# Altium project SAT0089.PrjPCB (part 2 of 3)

## Sheet CAMERA 2.SchDoc
size 431 x 279 mm; Date: Not shown in title block; ApprovedBy: Not shown in title block; CheckedBy: Not shown in title block; Author: Not shown in title block; CompanyName: Not shown in title block; DrawnBy: G. Fiolic; Engineer: Not shown in title block; Organization: Not shown in title block; Address1: Not shown in title block; Address2: Not shown in title block; Address3: Not shown in title block; Address4: Not shown in title block; DocumentNumber: 6; Revision: Use project parameter SCH_Rev; SheetNumber: 6; SheetTotal: 11; PageSetup: Record=PageOptions|CenterHorizontal=True|CenterVertical=True|PrintScale=1.00|XCorrection=1.00|YCorrection=1.00|PrintKind=0|BorderSize=5000000|LeftOffset=0|BottomOffset=0|Orientation=2|PaperLength=1000|PaperWidth=1000|Scale=100|PaperSource=15|PrintQuality=600|MediaType=1|DitherType=10|PaperKind=Letter|PrintScaleMode=1
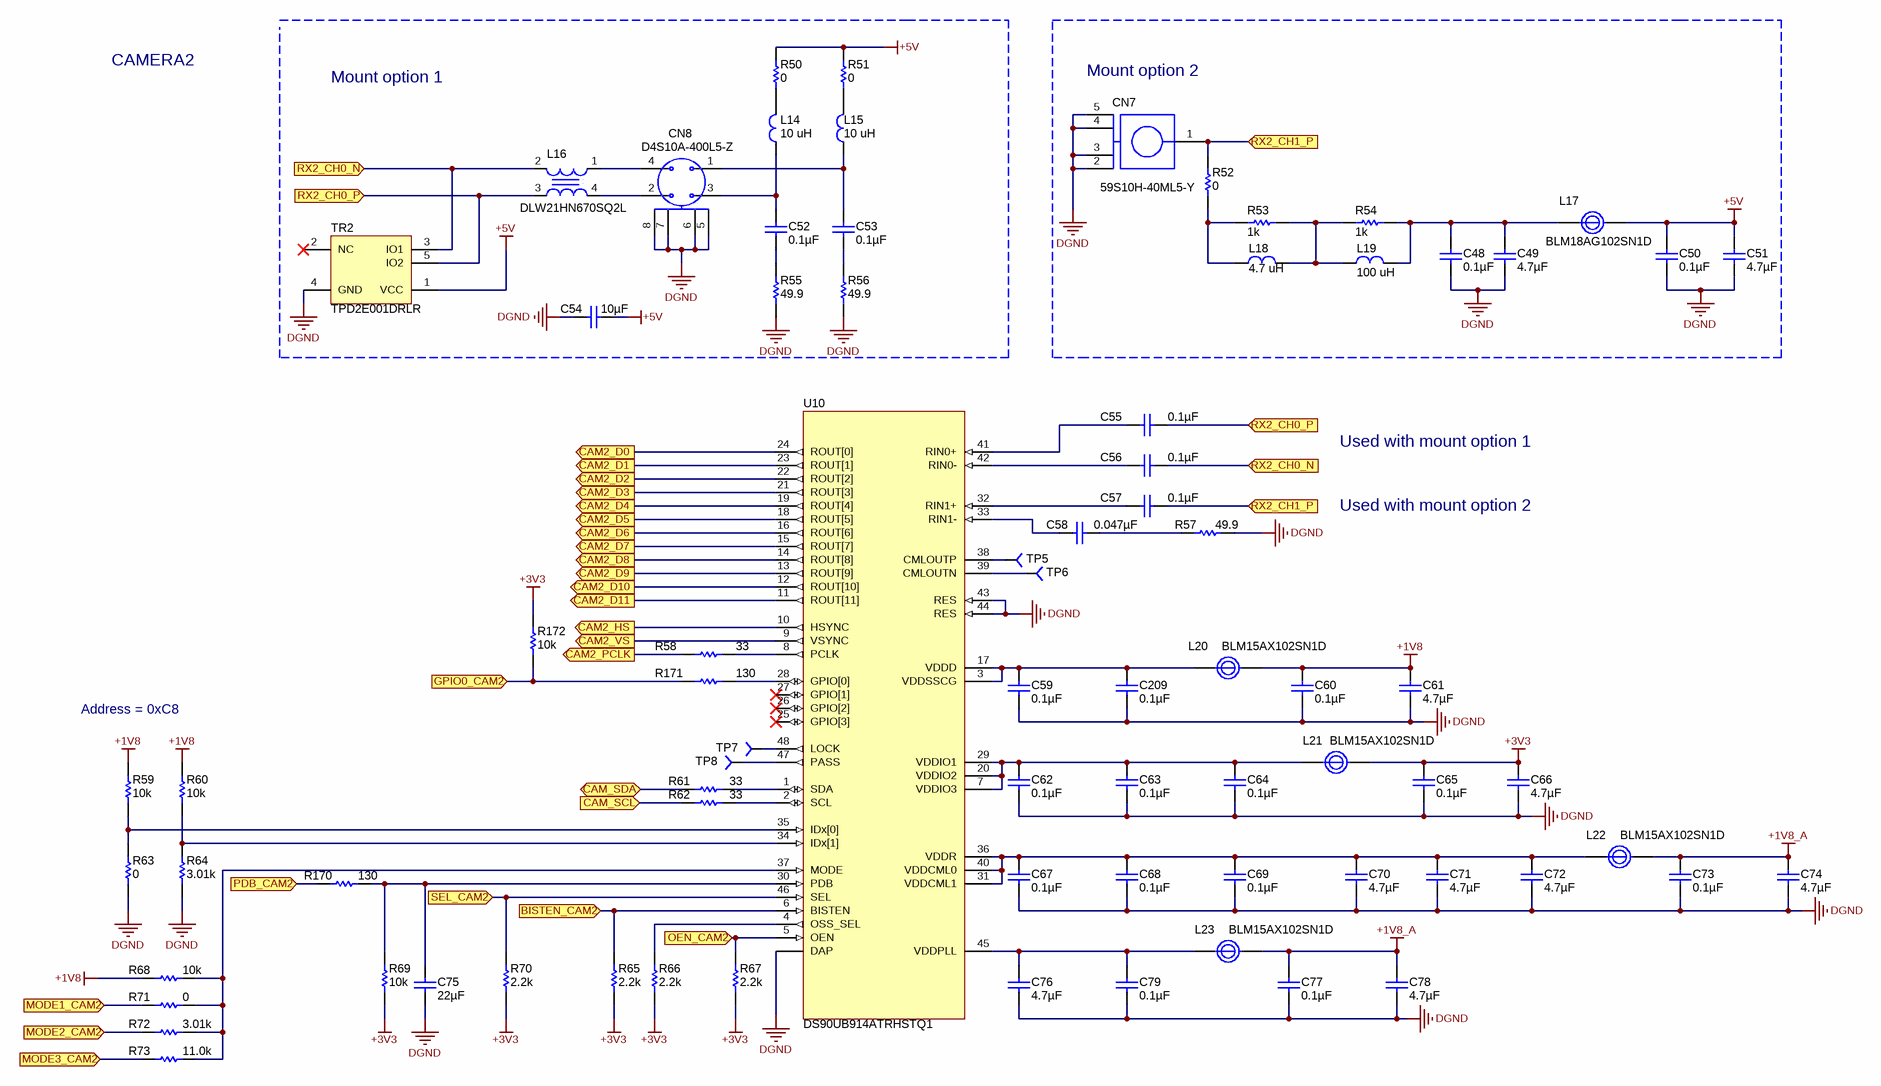
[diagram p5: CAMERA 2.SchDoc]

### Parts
C48  ValueDisplayed: 0.1µF  [0402L]  (hidden comment: GRM155R71C104KA88D)
C49  value 4.7µF  [0603L]  (hidden comment: GRM188R61E475KE11D)
C50  ValueDisplayed: 0.1µF  [0402L]  (hidden comment: GRM155R71C104KA88D)
C51  value 4.7µF  [0603L]  (hidden comment: GRM188R61E475KE11D)
C52  value 0.1µF  [0603L]  (hidden comment: GRM188R72A104KA35D)
C53  value 0.1µF  [0603L]  (hidden comment: GRM188R72A104KA35D)
C54  ValueDisplayed: 10µF  [0805L]  (hidden comment: GRM21BR61C106KE15L)
C55  ValueDisplayed: 0.1µF  [0402L]  (hidden comment: GRM155R71C104KA88D)
C56  ValueDisplayed: 0.1µF  [0402L]  (hidden comment: GRM155R71C104KA88D)
C57  ValueDisplayed: 0.1µF  [0402L]  (hidden comment: GRM155R71C104KA88D)
C58  ValueDisplayed: 0.047µF  [0402L]  (hidden comment: GRM155R71C473KA01D)
C59  ValueDisplayed: 0.1µF  [0402L]  (hidden comment: GRM155R71C104KA88D)
C60  ValueDisplayed: 0.1µF  [0402L]  (hidden comment: GRM155R71C104KA88D)
C61  value 4.7µF  [0603L]  (hidden comment: GRM188R61E475KE11D)
C62  ValueDisplayed: 0.1µF  [0402L]  (hidden comment: GRM155R71C104KA88D)
C63  ValueDisplayed: 0.1µF  [0402L]  (hidden comment: GRM155R71C104KA88D)
C64  ValueDisplayed: 0.1µF  [0402L]  (hidden comment: GRM155R71C104KA88D)
C65  ValueDisplayed: 0.1µF  [0402L]  (hidden comment: GRM155R71C104KA88D)
C66  value 4.7µF  [0603L]  (hidden comment: GRM188R61E475KE11D)
C67  ValueDisplayed: 0.1µF  [0402L]  (hidden comment: GRM155R71C104KA88D)
C68  ValueDisplayed: 0.1µF  [0402L]  (hidden comment: GRM155R71C104KA88D)
C69  ValueDisplayed: 0.1µF  [0402L]  (hidden comment: GRM155R71C104KA88D)
C70  value 4.7µF  [0603L]  (hidden comment: GRM188R61E475KE11D)
C71  value 4.7µF  [0603L]  (hidden comment: GRM188R61E475KE11D)
C72  value 4.7µF  [0603L]  (hidden comment: GRM188R61E475KE11D)
C73  ValueDisplayed: 0.1µF  [0402L]  (hidden comment: GRM155R71C104KA88D)
C74  value 4.7µF  [0603L]  (hidden comment: GRM188R61E475KE11D)
C75  ValueDisplayed: 22µF  [0805L]  (hidden comment: JMK212BJ226KG-T)
C76  value 4.7µF  [0603L]  (hidden comment: GRM188R61E475KE11D)
C77  ValueDisplayed: 0.1µF  [0402L]  (hidden comment: GRM155R71C104KA88D)
C78  value 4.7µF  [0603L]  (hidden comment: GRM188R61E475KE11D)
C79  ValueDisplayed: 0.1µF  [0402L]  (hidden comment: GRM155R71C104KA88D)
C209  ValueDisplayed: 0.1µF  [0402L]  (hidden comment: GRM155R71C104KA88D)
CN7  59S10H-40ML5-Y  [59S10H-40ML5-Y]
CN8  D4S10A-400L5-Z  [D4S10A-400L5-Z]
L14  ValueDisplayed: 10 uH  [1008PS-103KLB]  (hidden comment: 1008PS-103KLB)
L15  ValueDisplayed: 10 uH  [1008PS-103KLB]  (hidden comment: 1008PS-103KLB)
L16  DLW21HN670SQ2L  [DLW21HN670SQ2L]
L17  BLM18AG102SN1D  [0603L]
L18  ValueDisplayed: 4.7 uH  [1008PS-472KLB]  (hidden comment: 1008PS-472KLB)
L19  ValueDisplayed: 100 uH  [MSS7341T-104MLB]  (hidden comment: MSS7341T-104MLB)
L20  BLM15AX102SN1D  [0402L]
L21  BLM15AX102SN1D  [0402L]
L22  BLM15AX102SN1D  [0402L]
L23  BLM15AX102SN1D  [0402L]
R50  value 0  [0805L]  (hidden comment: CRCW08050000Z0EA)
R51  value 0  [0805L]  (hidden comment: CRCW08050000Z0EA)
R52  value 0  [0805L]  (hidden comment: CRCW08050000Z0EA)
R53  value 1k  [0603L]  (hidden comment: RC0603JR-071KL)
R54  value 1k  [0603L]  (hidden comment: RC0603JR-071KL)
R55  value 49.9  [0402L]  (hidden comment: CRCW040249R9FKED)
R56  value 49.9  [0402L]  (hidden comment: CRCW040249R9FKED)
R57  value 49.9  [0402L]  (hidden comment: CRCW040249R9FKED)
R58  value 33  [0402L]  (hidden comment: CRCW040233R0JNED)
R59  value 10k  [0402L]  (hidden comment: ERA-2AEB103X)
R60  value 10k  [0402L]  (hidden comment: ERA-2AEB103X)
R61  value 33  [0402L]  (hidden comment: CRCW040233R0JNED)
R62  value 33  [0402L]  (hidden comment: CRCW040233R0JNED)
R63  value 0  [0402L]  (hidden comment: CRCW04020000Z0ED)
R64  value 3.01k  [0402L]  (hidden comment: CRCW04023K01FKED)
R65  value 2.2k  [0402L]  (hidden comment: CRCW04022K20JNED)
R66  value 2.2k  [0402L]  (hidden comment: CRCW04022K20JNED)
R67  value 2.2k  [0402L]  (hidden comment: CRCW04022K20JNED)
R68  value 10k  [0402L]  (hidden comment: ERA-2AEB103X)
R69  value 10k  [0402L]  (hidden comment: ERA-2AEB103X)
R70  value 2.2k  [0402L]  (hidden comment: CRCW04022K20JNED)
R71  value 0  [0402L]  (hidden comment: CRCW04020000Z0ED)
R72  value 3.01k  [0402L]  (hidden comment: CRCW04023K01FKED)
R73  value 11.0k  [0402L]  (hidden comment: CRCW040211K0FKED)
R170  value 130  [0402L]  (hidden comment: CRCW0402130RJNED)
R171  value 130  [0402L]  (hidden comment: CRCW0402130RJNED)
R172  value 10k  [0402L]  (hidden comment: ERA-2AEB103X)
TP5  STD  [TP-032_RND]  (value not drawn)
TP6  STD  [TP-032_RND]  (value not drawn)
TP7  STD  [TP-032_RND]  (value not drawn)
TP8  STD  [TP-032_RND]  (value not drawn)
TR2  TPD2E001DRLR  [DRL0005A]
U10  DS90UB914ATRHSTQ1  [RHS0048A]

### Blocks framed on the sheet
Mount option 2: C48-C51 CN7 L17-L19 R52-R54

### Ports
BISTEN_CAM2 (in), CAM2_D0 (out), CAM2_D1 (out), CAM2_D2 (out), CAM2_D3 (out), CAM2_D4 (out), CAM2_D5 (out), CAM2_D6 (out), CAM2_D7 (out), CAM2_D8 (out), CAM2_D9 (out), CAM2_D10 (out), CAM2_D11 (out), CAM2_HS (out), CAM2_PCLK (out), CAM2_VS (out), CAM_SCL (in), CAM_SDA (bidir), GPIO0_CAM2 (in), MODE1_CAM2 (in), MODE2_CAM2 (in), MODE3_CAM2 (in), OEN_CAM2 (in), PDB_CAM2 (in), RX2_CH0_N (in), RX2_CH0_P (in), RX2_CH1_P (in), SEL_CAM2 (in)

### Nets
+1V8: C60.1 C61.1 L20.2 R59.1 R60.1 R68.1
+1V8_A: C73.1 C74.1 C77.1 C78.1 L22.2 L23.2
+3V3: C65.1 C66.1 L21.2 R65.2 R66.2 R67.2 R69.1 R70.1 R172.1
+5V: C50.1 C51.1 C54.1 L17.2 R50.2 R51.2 TR2.1(VCC)
DGND: C48.2 C49.2 C50.2 C51.2 C54.2 C59.2 C60.2 C61.2 C62.2 C63.2 C64.2 C65.2 C66.2 C67.2 C68.2 C69.2 C70.2 C71.2 C72.2 C73.2 C74.2 C75.2 C76.2 C77.2 C78.2 C79.2 C209.2 CN7.2 CN7.3 CN7.4 CN7.5 CN8.5 CN8.6 CN8.7 CN8.8 R55.1 R56.1 R57.2 R63.2 R64.2 TR2.4(GND) U10.43(RES) U10.44(RES) U10.49(DAP)
BISTEN_CAM2: R65.1 U10.6(BISTEN) ; port BISTEN_CAM2
CAM2_D0: U10.24(ROUT[0]) ; port CAM2_D0
CAM2_D1: U10.23(ROUT[1]) ; port CAM2_D1
CAM2_D2: U10.22(ROUT[2]) ; port CAM2_D2
CAM2_D3: U10.21(ROUT[3]) ; port CAM2_D3
CAM2_D4: U10.19(ROUT[4]) ; port CAM2_D4
CAM2_D5: U10.18(ROUT[5]) ; port CAM2_D5
CAM2_D6: U10.16(ROUT[6]) ; port CAM2_D6
CAM2_D7: U10.15(ROUT[7]) ; port CAM2_D7
CAM2_D8: U10.14(ROUT[8]) ; port CAM2_D8
CAM2_D9: U10.13(ROUT[9]) ; port CAM2_D9
CAM2_D10: U10.12(ROUT[10]) ; port CAM2_D10
CAM2_D11: U10.11(ROUT[11]) ; port CAM2_D11
CAM2_HS: U10.10(HSYNC) ; port CAM2_HS
CAM2_PCLK: R58.1 ; port CAM2_PCLK
CAM2_VS: U10.9(VSYNC) ; port CAM2_VS
CAM_SCL: R62.1 ; port CAM_SCL
CAM_SDA: R61.2 ; port CAM_SDA
GPIO0_CAM2: R171.1 R172.2 ; port GPIO0_CAM2
MODE1_CAM2: R71.1 ; port MODE1_CAM2
MODE2_CAM2: R72.1 ; port MODE2_CAM2
MODE3_CAM2: R73.1 ; port MODE3_CAM2
OEN_CAM2: R67.1 U10.5(OEN) ; port OEN_CAM2
PDB_CAM2: R170.1 ; port PDB_CAM2
RX2_CH0_N: C56.2 L16.2(IN2) TR2.3(IO1) ; port RX2_CH0_N
RX2_CH0_P: C55.2 L16.3(OUT2) TR2.5(IO2) ; port RX2_CH0_P
RX2_CH1_P: C57.2 CN7.1 R52.2 ; port RX2_CH1_P
SEL_CAM2: R70.2 U10.46(SEL) ; port SEL_CAM2
NetC48_1: C48.1 C49.1 L17.1 L19.2 R54.2
NetC52_1: C52.1 CN8.3 L14.1
NetC52_2: C52.2 R55.2
NetC53_1: C53.1 CN8.1 L15.1
NetC53_2: C53.2 R56.2
NetC55_1: C55.1 U10.41(RIN0+)
NetC56_1: C56.1 U10.42(RIN0-)
NetC57_1: C57.1 U10.32(RIN1+)
NetC58_1: C58.1 R57.1
NetC58_2: C58.2 U10.33(RIN1-)
NetC59_1: C59.1 C209.1 L20.1 U10.3(VDDSSCG) U10.17(VDDD)
NetC62_1: C62.1 C63.1 C64.1 L21.1 U10.7(VDDIO3) U10.20(VDDIO2) U10.29(VDDIO1)
NetC67_1: C67.1 C68.1 C69.1 C70.1 C71.1 C72.1 L22.1 U10.31(VDDCML1) U10.36(VDDR) U10.40(VDDCML0)
NetC75_1: C75.1 R69.2 R170.2 U10.30(PDB)
NetC76_1: C76.1 C79.1 L23.1 U10.45(VDDPLL)
NetCN8_2: CN8.2 L16.4(OUT1)
NetCN8_4: CN8.4 L16.1(IN1)
NetL14_2: L14.2 R50.1
NetL15_2: L15.2 R51.1
NetL18_1: L18.1 R52.1 R53.1
NetL18_2: L18.2 L19.1 R53.2 R54.1
NetR58_2: R58.2 U10.8(PCLK)
NetR59_2: R59.2 R63.1 U10.35(IDx[0])
NetR60_2: R60.2 R64.1 U10.34(IDx[1])
NetR61_1: R61.1 U10.1(SDA)
NetR62_2: R62.2 U10.2(SCL)
NetR66_1: R66.1 U10.4(OSS_SEL)
NetR68_2: R68.2 R71.2 R72.2 R73.2 U10.37(MODE)
NetR171_2: R171.2 U10.28(GPIO[0])
NetTP5_1: TP5.1 U10.38(CMLOUTP)
NetTP6_1: TP6.1 U10.39(CMLOUTN)
NetTP7_1: TP7.1 U10.48(LOCK)
NetTP8_1: TP8.1 U10.47(PASS)

Not connected (* = marked no-connect by the designer): TR2 2(NC)*; U10 25(GPIO[3])* 26(GPIO[2])* 27(GPIO[1])*

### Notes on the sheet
- CAMERA2
- Mount option 1
- Used with mount option 1
- Used with mount option 2
- Address = 0xC8

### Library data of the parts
C48 C50 C55-C57 C59 C60 C62-C65 C67-C69 C73 C77 C79 C209 = GRM155R71C104KA88D: CAP, CERM, 0.1uF, 16V, +/-10%, X7R, 0402; Manufacturer: MuRata; Polarized: N; CompType: Capacitor; U/M: EA; Cap_F: 0.0000001; Tolerance_%: 10; Value1: Unknown; VDC_V: 16; TaMin_C: -55; TaMax_C: 125; Cap_Case: 0402
C49 C51 C61 C66 C70-C72 C74 C76 C78 = GRM188R61E475KE11D: CAP CER 4.7UF 25V 10% X5R 0603; Manufacturer: Murata Electronics North America
C52 C53 = GRM188R72A104KA35D: CAP CER 0.1UF 100V 10% X7R 0603; Manufacturer: Murata Electronics North America
C54 = GRM21BR61C106KE15L: CAP, CERM, 10uF, 16V, +/-10%, X5R, 0805; Manufacturer: MuRata; Polarized: N; CompType: Capacitor; U/M: EA; Cap_F: 0.00001; Tolerance_%: 10; ESR_Ohm: 0.008; Value1: 0.008 ohm; VDC_V: 16; TaMin_C: -55; TaMax_C: 85; Cap_Case: 0805
C58 = GRM155R71C473KA01D: CAP, CERM, 0.047uF, 16V, +/-10%, X7R, 0402; Manufacturer: MuRata; Polarized: N; CompType: Capacitor; U/M: EA; Cap_F: 0.000000047; Tolerance_%: 10; Value1: Unknown; VDC_V: 16; TaMin_C: -55; TaMax_C: 125; Cap_Case: 0402
C75 = JMK212BJ226KG-T: CAP, CERM, 22uF, 6.3V, +/-10%, X5R, 0805; Manufacturer: Taiyo Yuden; Polarized: N; CompType: Capacitor; U/M: EA; Cap_F: 0.000022; Tolerance_%: 10; ESR_Ohm: 0.002; Value1: 0.002 ohm; VDC_V: 6.3; TaMin_C: -55; TaMax_C: 85; Cap_Case: 0805
CN7 = 59S10H-40ML5-Y: Straight Plug PCB; Manufacturer: Rosenberger; SymbolVersion: use current date i.e. 2008-05-20; SymbolCreator: Use a-id; CompType: SMA connector; U/M: EA, IN, or GM
CN8 = D4S10A-400L5-Z: Straight Plug; Manufacturer: Rosenberger
L14 L15 = 1008PS-103KLB: Fixed Inductors Power Inductor 10 uH 10 % 0.59 A; Manufacturer: Coilcraft; Material: Ferrite; Maximum DC Current: 590 mA; Maximum DC Resistance: 920 mOhms; Q Minimum: 38; Self Resonant Frequency: 105 MHz; Shielding: Shielded; Tolerance_%: 10 %; Case Height: 2.74 mm; Case Length: 3.81 mm; Case Width: 3.78 mm; Test Frequency: 100 kHz; Product Status: New at Mouser
L16 = DLW21HN670SQ2L: CHOKE COMMON MODE 67 OHM 0805; Manufacturer: Murata Electronics North America; Filter Type: Data, Signal Line; Number of Lines: 2; Irms: 330mA; DCR_Ohm: 350 mOhm Max; Impedance: 67 Ohm
L17 = BLM18AG102SN1D: FERRITE CHIP 1000 OHM 400MA 0603; Manufacturer: Murata Electronics North America; Impedance @ Frequency: 1 kOhm @ 100MHz; DCR_Ohm: 500 mOhm Max; Filter Type: Differential Mode - Single
L18 = 1008PS-472KLB: Fixed Inductors Power Inductor 4.7 uH 10 % 0.95 A; Manufacturer: Coilcraft; Material: Ferrite; Maximum DC Current: 950 mA; Maximum DC Resistance: 350 mOhms; Q Minimum: 38; Self Resonant Frequency: 160 MHz; Shielding: Shielded; Tolerance_%: 10 %; Case Height: 2.74 mm; Case Length: 3.81 mm; Case Width: 3.78 mm; Test Frequency: 100 kHz
L19 = MSS7341T-104MLB: Fixed Inductors Power Inductor 100 uH 20 % 1.15 A; Manufacturer: Coilcraft; Material: Ferrite; Maximum DC Current: 1.15 A; Maximum DC Resistance: 310 mOhms; Self Resonant Frequency: 7.2 MHz; Shielding: Shielded; Tolerance_%: 20 %; Case Height: 4.1 mm; Case Length: 7.3 mm; Test Frequency: 100 kHz
L20-L23 = BLM15AX102SN1D: FERRITE CHIP 1000 OHM 0402; Manufacturer: Murata Electronics North America; Impedance @ Frequency: 1 kOhm @ 100MHz; Current Rating: 350mA; DCR_Ohm: 490 mOhm Max; Filter Type: Differential Mode - Single
R50-R52 = CRCW08050000Z0EA: RES, 0 ohm, 5%, 0.125W, 0805; Manufacturer: Vishay-Dale; CompType: Resistor; Value_Code: 0000; Tolerance_%: 5; Power_W: 0.125; VDC_V: 150; TempCo: 200 ppm/C; EIA_Code: E24; U/M: EA
R53 R54 = RC0603JR-071KL: RES 1.0K OHM 1/10W 5% 0603 SMD; Manufacturer: Yageo; Power_W: 0.1W, 1/10W; TempCo: ±100ppm/°C
R55-R57 = CRCW040249R9FKED: RES, 49.9 ohm, 1%, 0.063W, 0402; Manufacturer: Vishay-Dale; CompType: Resistor; Value_Code: 49R9; Tolerance_%: 1; Power_W: 0.063; VDC_V: 50; TempCo: 100 ppm/C; EIA_Code: E96; U/M: EA
R58 R61 R62 = CRCW040233R0JNED: RES, 33 ohm, 5%, 0.063W, 0402; Manufacturer: Vishay-Dale; CompType: Resistor; Value_Code: 33R0; Tolerance_%: 5; Power_W: 0.063; VDC_V: 50; TempCo: 200 ppm/C; EIA_Code: E24; U/M: EA
R59 R60 R68 R69 R172 = ERA-2AEB103X: RES 10K OHM 1/16W .1% 0402 SMD; Manufacturer: Panasonic Electronic Components; Tolerance_%: ±0.1%; Power_W: 0.063W, 1/16W; TempCo: ±25ppm/°C
R63 R71 = CRCW04020000Z0ED: RES, 0 ohm, 5%, 0.063W, 0402; Manufacturer: Vishay-Dale; CompType: Resistor; Value_Code: 0000; Tolerance_%: 5; Power_W: 0.063; VDC_V: 50; TempCo: 200 ppm/C; EIA_Code: E24; U/M: EA
R64 R72 = CRCW04023K01FKED: RES, 3.01k ohm, 1%, 0.063W, 0402; Manufacturer: Vishay-Dale; CompType: Resistor; Res_ohm: 3010; Value_Code: 3k01; Tolerance_%: 1; Power_W: 0.063; VDC_V: 50; TempCo: 100 ppm/C; EIA_Code: E96; U/M: EA
R65-R67 R70 = CRCW04022K20JNED: RES, 2.2k ohm, 5%, 0.063W, 0402; Manufacturer: Vishay-Dale; CompType: Resistor; Res_ohm: 2200; Value_Code: 2k20; Tolerance_%: 5; Power_W: 0.063; VDC_V: 50; TempCo: 200 ppm/C; EIA_Code: E24; U/M: EA
R73 = CRCW040211K0FKED: RES, 11.0k ohm, 1%, 0.063W, 0402; Manufacturer: Vishay-Dale; CompType: Resistor; Res_ohm: 11000; Value_Code: 11k0; Tolerance_%: 1; Power_W: 0.063; VDC_V: 50; TempCo: 100 ppm/C; EIA_Code: E96; U/M: EA
R170 R171 = CRCW0402130RJNED: RES, 130 ohm, 5%, 0.063W, 0402; Manufacturer: Vishay-Dale; CompType: Resistor; Value_Code: 130R; Tolerance_%: 5; Power_W: 0.063; VDC_V: 50; TempCo: 200 ppm/C; EIA_Code: E24; U/M: EA
TP5-TP8 = TP-032_RND: Test Point, O.032 Hole
TR2 = TPD2E001DRLR: Low-Capacitance + / - 15 kV ESD-Protection Array for High-Speed Data Interfaces, 2 Channels, -40 to +85 degC, 5-pin SOT (DRL), Green (RoHS & no Sb/Br); Manufacturer: Texas Instruments; Alternate Manufacturer: None; Alternate PartNumber: Equivalent; Breakdown Voltage(Min)(V): 11; IEC 61000-4-2 Air-Gap(+/- kV): 15; IEC 61000-4-2 Contact(+/- kV): 8; IO Capacitance(Typ)(pF): 1.5; IO Leakage Current(nA): 1; SubFamily: ESD Solution; USB High Speed: TRUE
U10 = DS90UB914ATRHSTQ1: FPD-Link III Serializer and Deserializer, RHS0048A; Alternate Manufacturer: None; Manufacturer: Texas Instruments; SymbolCreator: a0799628; CompType: IC; U/M: EA

## Sheet CAMERA 3.SchDoc
size 431 x 279 mm; Date: Not shown in title block; ApprovedBy: Not shown in title block; CheckedBy: Not shown in title block; Author: Not shown in title block; CompanyName: Not shown in title block; DrawnBy: G. Fiolic; Engineer: Not shown in title block; Organization: Not shown in title block; Address1: Not shown in title block; Address2: Not shown in title block; Address3: Not shown in title block; Address4: Not shown in title block; DocumentNumber: 7; Revision: Use project parameter SCH_Rev; SheetNumber: 7; SheetTotal: 11; PageSetup: Record=PageOptions|CenterHorizontal=True|CenterVertical=True|PrintScale=1.00|XCorrection=1.00|YCorrection=1.00|PrintKind=0|BorderSize=5000000|LeftOffset=0|BottomOffset=0|Orientation=2|PaperLength=1000|PaperWidth=1000|Scale=100|PaperSource=15|PrintQuality=600|MediaType=1|DitherType=10|PaperKind=Letter|PrintScaleMode=1
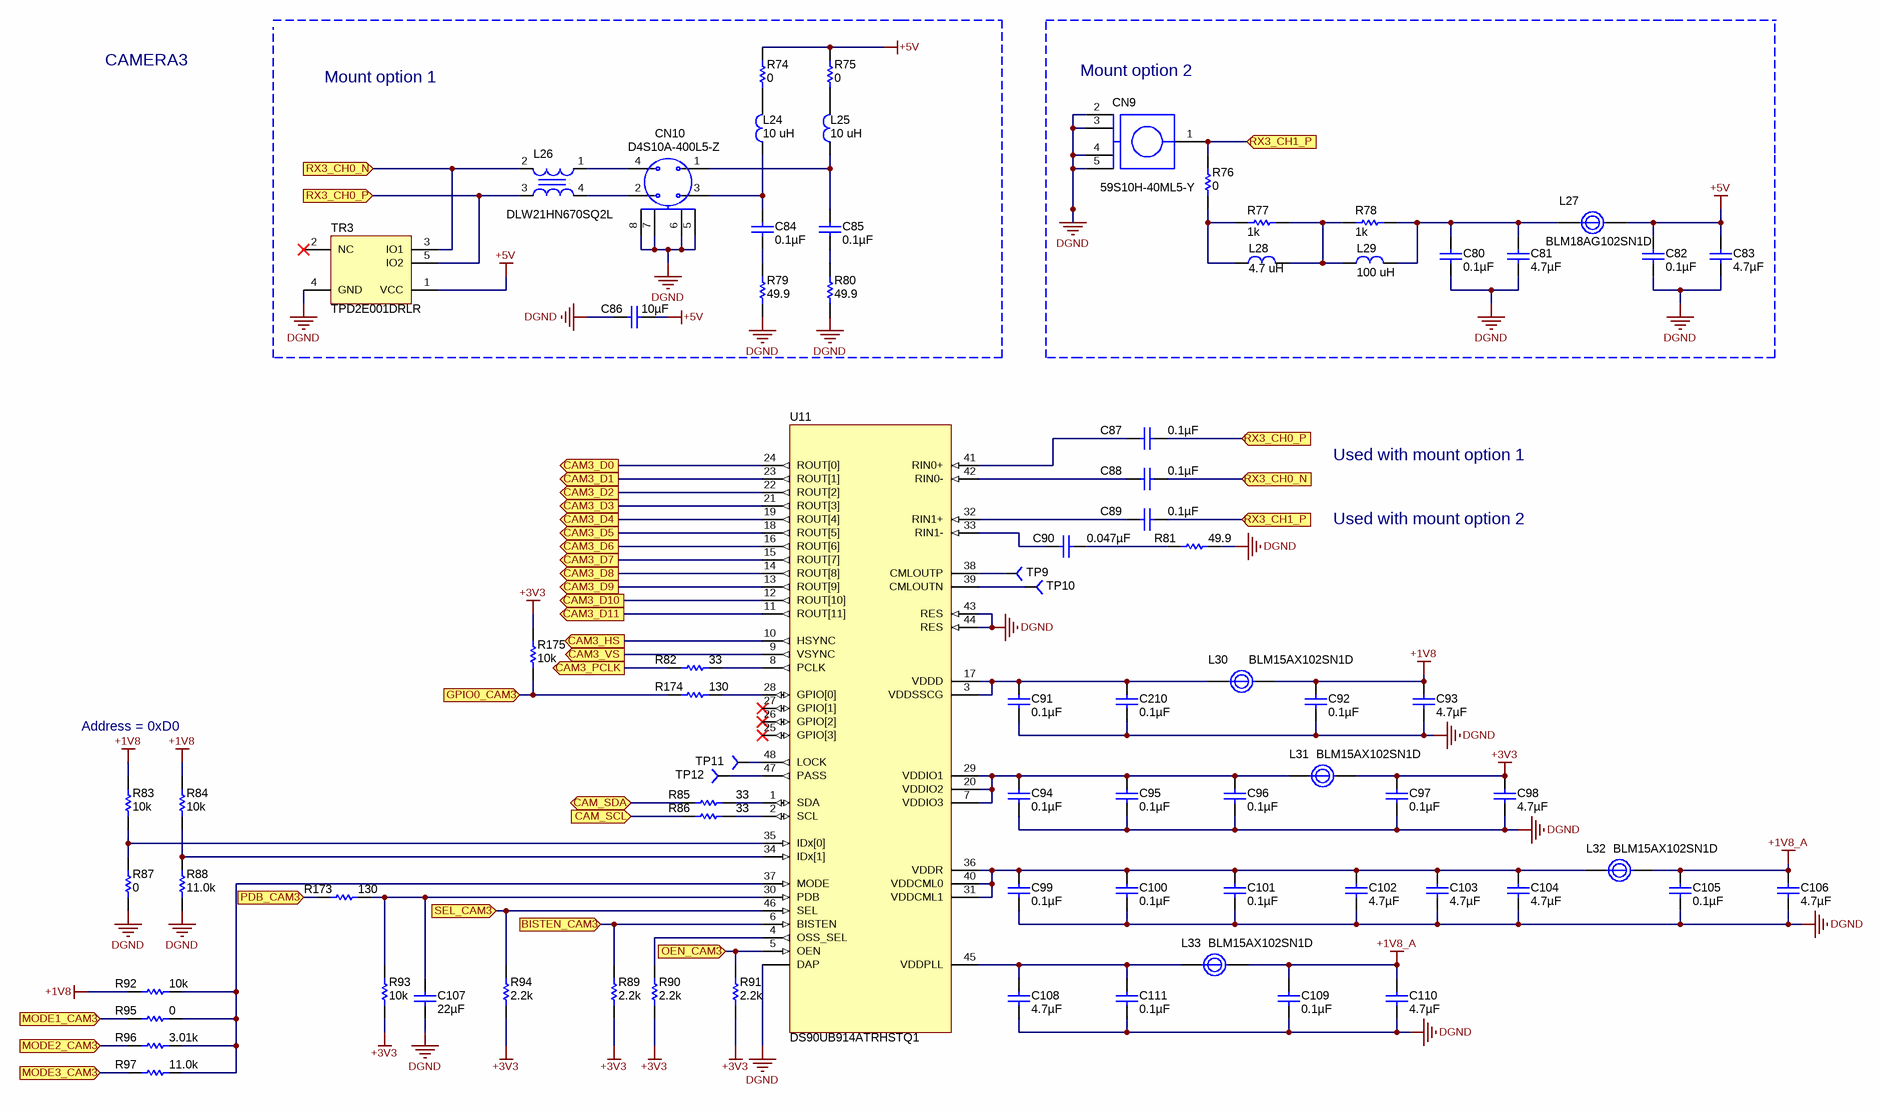
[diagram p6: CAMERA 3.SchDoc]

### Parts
C80  ValueDisplayed: 0.1µF  [0402L]  (hidden comment: GRM155R71C104KA88D)
C81  value 4.7µF  [0603L]  (hidden comment: GRM188R61E475KE11D)
C82  ValueDisplayed: 0.1µF  [0402L]  (hidden comment: GRM155R71C104KA88D)
C83  value 4.7µF  [0603L]  (hidden comment: GRM188R61E475KE11D)
C84  value 0.1µF  [0603L]  (hidden comment: GRM188R72A104KA35D)
C85  value 0.1µF  [0603L]  (hidden comment: GRM188R72A104KA35D)
C86  ValueDisplayed: 10µF  [0805L]  (hidden comment: GRM21BR61C106KE15L)
C87  ValueDisplayed: 0.1µF  [0402L]  (hidden comment: GRM155R71C104KA88D)
C88  ValueDisplayed: 0.1µF  [0402L]  (hidden comment: GRM155R71C104KA88D)
C89  ValueDisplayed: 0.1µF  [0402L]  (hidden comment: GRM155R71C104KA88D)
C90  ValueDisplayed: 0.047µF  [0402L]  (hidden comment: GRM155R71C473KA01D)
C91  ValueDisplayed: 0.1µF  [0402L]  (hidden comment: GRM155R71C104KA88D)
C92  ValueDisplayed: 0.1µF  [0402L]  (hidden comment: GRM155R71C104KA88D)
C93  value 4.7µF  [0603L]  (hidden comment: GRM188R61E475KE11D)
C94  ValueDisplayed: 0.1µF  [0402L]  (hidden comment: GRM155R71C104KA88D)
C95  ValueDisplayed: 0.1µF  [0402L]  (hidden comment: GRM155R71C104KA88D)
C96  ValueDisplayed: 0.1µF  [0402L]  (hidden comment: GRM155R71C104KA88D)
C97  ValueDisplayed: 0.1µF  [0402L]  (hidden comment: GRM155R71C104KA88D)
C98  value 4.7µF  [0603L]  (hidden comment: GRM188R61E475KE11D)
C99  ValueDisplayed: 0.1µF  [0402L]  (hidden comment: GRM155R71C104KA88D)
C100  ValueDisplayed: 0.1µF  [0402L]  (hidden comment: GRM155R71C104KA88D)
C101  ValueDisplayed: 0.1µF  [0402L]  (hidden comment: GRM155R71C104KA88D)
C102  value 4.7µF  [0603L]  (hidden comment: GRM188R61E475KE11D)
C103  value 4.7µF  [0603L]  (hidden comment: GRM188R61E475KE11D)
C104  value 4.7µF  [0603L]  (hidden comment: GRM188R61E475KE11D)
C105  ValueDisplayed: 0.1µF  [0402L]  (hidden comment: GRM155R71C104KA88D)
C106  value 4.7µF  [0603L]  (hidden comment: GRM188R61E475KE11D)
C107  ValueDisplayed: 22µF  [0805L]  (hidden comment: JMK212BJ226KG-T)
C108  value 4.7µF  [0603L]  (hidden comment: GRM188R61E475KE11D)
C109  ValueDisplayed: 0.1µF  [0402L]  (hidden comment: GRM155R71C104KA88D)
C110  value 4.7µF  [0603L]  (hidden comment: GRM188R61E475KE11D)
C111  ValueDisplayed: 0.1µF  [0402L]  (hidden comment: GRM155R71C104KA88D)
C210  ValueDisplayed: 0.1µF  [0402L]  (hidden comment: GRM155R71C104KA88D)
CN9  59S10H-40ML5-Y  [59S10H-40ML5-Y]
CN10  D4S10A-400L5-Z  [D4S10A-400L5-Z]
L24  ValueDisplayed: 10 uH  [1008PS-103KLB]  (hidden comment: 1008PS-103KLB)
L25  ValueDisplayed: 10 uH  [1008PS-103KLB]  (hidden comment: 1008PS-103KLB)
L26  DLW21HN670SQ2L  [DLW21HN670SQ2L]
L27  BLM18AG102SN1D  [0603L]
L28  ValueDisplayed: 4.7 uH  [1008PS-472KLB]  (hidden comment: 1008PS-472KLB)
L29  ValueDisplayed: 100 uH  [MSS7341T-104MLB]  (hidden comment: MSS7341T-104MLB)
L30  BLM15AX102SN1D  [0402L]
L31  BLM15AX102SN1D  [0402L]
L32  BLM15AX102SN1D  [0402L]
L33  BLM15AX102SN1D  [0402L]
R74  value 0  [0805L]  (hidden comment: CRCW08050000Z0EA)
R75  value 0  [0805L]  (hidden comment: CRCW08050000Z0EA)
R76  value 0  [0805L]  (hidden comment: CRCW08050000Z0EA)
R77  value 1k  [0603L]  (hidden comment: RC0603JR-071KL)
R78  value 1k  [0603L]  (hidden comment: RC0603JR-071KL)
R79  value 49.9  [0402L]  (hidden comment: CRCW040249R9FKED)
R80  value 49.9  [0402L]  (hidden comment: CRCW040249R9FKED)
R81  value 49.9  [0402L]  (hidden comment: CRCW040249R9FKED)
R82  value 33  [0402L]  (hidden comment: CRCW040233R0JNED)
R83  value 10k  [0402L]  (hidden comment: ERA-2AEB103X)
R84  value 10k  [0402L]  (hidden comment: ERA-2AEB103X)
R85  value 33  [0402L]  (hidden comment: CRCW040233R0JNED)
R86  value 33  [0402L]  (hidden comment: CRCW040233R0JNED)
R87  value 0  [0402L]  (hidden comment: CRCW04020000Z0ED)
R88  value 11.0k  [0402L]  (hidden comment: CRCW040211K0FKED)
R89  value 2.2k  [0402L]  (hidden comment: CRCW04022K20JNED)
R90  value 2.2k  [0402L]  (hidden comment: CRCW04022K20JNED)
R91  value 2.2k  [0402L]  (hidden comment: CRCW04022K20JNED)
R92  value 10k  [0402L]  (hidden comment: ERA-2AEB103X)
R93  value 10k  [0402L]  (hidden comment: ERA-2AEB103X)
R94  value 2.2k  [0402L]  (hidden comment: CRCW04022K20JNED)
R95  value 0  [0402L]  (hidden comment: CRCW04020000Z0ED)
R96  value 3.01k  [0402L]  (hidden comment: CRCW04023K01FKED)
R97  value 11.0k  [0402L]  (hidden comment: CRCW040211K0FKED)
R173  value 130  [0402L]  (hidden comment: CRCW0402130RJNED)
R174  value 130  [0402L]  (hidden comment: CRCW0402130RJNED)
R175  value 10k  [0402L]  (hidden comment: ERA-2AEB103X)
TP9  STD  [TP-032_RND]  (value not drawn)
TP10  STD  [TP-032_RND]  (value not drawn)
TP11  STD  [TP-032_RND]  (value not drawn)
TP12  STD  [TP-032_RND]  (value not drawn)
TR3  TPD2E001DRLR  [DRL0005A]
U11  DS90UB914ATRHSTQ1  [RHS0048A]

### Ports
BISTEN_CAM3 (in), CAM3_D0 (out), CAM3_D1 (out), CAM3_D2 (out), CAM3_D3 (out), CAM3_D4 (out), CAM3_D5 (out), CAM3_D6 (out), CAM3_D7 (out), CAM3_D8 (out), CAM3_D9 (out), CAM3_D10 (out), CAM3_D11 (out), CAM3_HS (out), CAM3_PCLK (out), CAM3_VS (out), CAM_SCL (in), CAM_SDA (bidir), GPIO0_CAM3 (in), MODE1_CAM3 (in), MODE2_CAM3 (in), MODE3_CAM3 (in), OEN_CAM3 (in), PDB_CAM3 (in), RX3_CH0_N (in), RX3_CH0_P (in), RX3_CH1_P (in), SEL_CAM3 (in)

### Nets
+1V8: C92.1 C93.1 L30.2 R83.1 R84.1 R92.1
+1V8_A: C105.1 C106.1 C109.1 C110.1 L32.2 L33.2
+3V3: C97.1 C98.1 L31.2 R89.2 R90.2 R91.2 R93.1 R94.1 R175.1
+5V: C82.1 C83.1 C86.1 L27.2 R74.2 R75.2 TR3.1(VCC)
DGND: C80.2 C81.2 C82.2 C83.2 C86.2 C91.2 C92.2 C93.2 C94.2 C95.2 C96.2 C97.2 C98.2 C99.2 C100.2 C101.2 C102.2 C103.2 C104.2 C105.2 C106.2 C107.2 C108.2 C109.2 C110.2 C111.2 C210.2 CN9.2 CN9.3 CN9.4 CN9.5 CN10.5 CN10.6 CN10.7 CN10.8 R79.1 R80.1 R81.2 R87.2 R88.2 TR3.4(GND) U11.43(RES) U11.44(RES) U11.49(DAP)
BISTEN_CAM3: R89.1 U11.6(BISTEN) ; port BISTEN_CAM3
CAM3_D0: U11.24(ROUT[0]) ; port CAM3_D0
CAM3_D1: U11.23(ROUT[1]) ; port CAM3_D1
CAM3_D2: U11.22(ROUT[2]) ; port CAM3_D2
CAM3_D3: U11.21(ROUT[3]) ; port CAM3_D3
CAM3_D4: U11.19(ROUT[4]) ; port CAM3_D4
CAM3_D5: U11.18(ROUT[5]) ; port CAM3_D5
CAM3_D6: U11.16(ROUT[6]) ; port CAM3_D6
CAM3_D7: U11.15(ROUT[7]) ; port CAM3_D7
CAM3_D8: U11.14(ROUT[8]) ; port CAM3_D8
CAM3_D9: U11.13(ROUT[9]) ; port CAM3_D9
CAM3_D10: U11.12(ROUT[10]) ; port CAM3_D10
CAM3_D11: U11.11(ROUT[11]) ; port CAM3_D11
CAM3_HS: U11.10(HSYNC) ; port CAM3_HS
CAM3_PCLK: R82.1 ; port CAM3_PCLK
CAM3_VS: U11.9(VSYNC) ; port CAM3_VS
CAM_SCL: R86.1 ; port CAM_SCL
CAM_SDA: R85.2 ; port CAM_SDA
GPIO0_CAM3: R174.1 R175.2 ; port GPIO0_CAM3
MODE1_CAM3: R95.1 ; port MODE1_CAM3
MODE2_CAM3: R96.1 ; port MODE2_CAM3
MODE3_CAM3: R97.1 ; port MODE3_CAM3
OEN_CAM3: R91.1 U11.5(OEN) ; port OEN_CAM3
PDB_CAM3: R173.1 ; port PDB_CAM3
RX3_CH0_N: C88.2 L26.2(IN2) TR3.3(IO1) ; port RX3_CH0_N
RX3_CH0_P: C87.2 L26.3(OUT2) TR3.5(IO2) ; port RX3_CH0_P
RX3_CH1_P: C89.2 CN9.1 R76.2 ; port RX3_CH1_P
SEL_CAM3: R94.2 U11.46(SEL) ; port SEL_CAM3
NetC80_1: C80.1 C81.1 L27.1 L29.2 R78.2
NetC84_1: C84.1 CN10.3 L24.1
NetC84_2: C84.2 R79.2
NetC85_1: C85.1 CN10.1 L25.1
NetC85_2: C85.2 R80.2
NetC87_1: C87.1 U11.41(RIN0+)
NetC88_1: C88.1 U11.42(RIN0-)
NetC89_1: C89.1 U11.32(RIN1+)
NetC90_1: C90.1 R81.1
NetC90_2: C90.2 U11.33(RIN1-)
NetC91_1: C91.1 C210.1 L30.1 U11.3(VDDSSCG) U11.17(VDDD)
NetC94_1: C94.1 C95.1 C96.1 L31.1 U11.7(VDDIO3) U11.20(VDDIO2) U11.29(VDDIO1)
NetC99_1: C99.1 C100.1 C101.1 C102.1 C103.1 C104.1 L32.1 U11.31(VDDCML1) U11.36(VDDR) U11.40(VDDCML0)
NetC107_1: C107.1 R93.2 R173.2 U11.30(PDB)
NetC108_1: C108.1 C111.1 L33.1 U11.45(VDDPLL)
NetCN10_2: CN10.2 L26.4(OUT1)
NetCN10_4: CN10.4 L26.1(IN1)
NetL24_2: L24.2 R74.1
NetL25_2: L25.2 R75.1
NetL28_1: L28.1 R76.1 R77.1
NetL28_2: L28.2 L29.1 R77.2 R78.1
NetR82_2: R82.2 U11.8(PCLK)
NetR83_2: R83.2 R87.1 U11.35(IDx[0])
NetR84_2: R84.2 R88.1 U11.34(IDx[1])
NetR85_1: R85.1 U11.1(SDA)
NetR86_2: R86.2 U11.2(SCL)
NetR90_1: R90.1 U11.4(OSS_SEL)
NetR92_2: R92.2 R95.2 R96.2 R97.2 U11.37(MODE)
NetR174_2: R174.2 U11.28(GPIO[0])
NetTP9_1: TP9.1 U11.38(CMLOUTP)
NetTP10_1: TP10.1 U11.39(CMLOUTN)
NetTP11_1: TP11.1 U11.48(LOCK)
NetTP12_1: TP12.1 U11.47(PASS)

Not connected (* = marked no-connect by the designer): TR3 2(NC)*; U11 25(GPIO[3])* 26(GPIO[2])* 27(GPIO[1])*

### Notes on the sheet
- CAMERA3
- Mount option 1
- (near CN9) Mount option 2
- Used with mount option 1
- Used with mount option 2
- Address = 0xD0

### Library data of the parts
C80 C82 C87-C89 C91 C92 C94-C97 C99-C101 C105 C109 C111 C210 = GRM155R71C104KA88D: as C48 on sheet CAMERA 2
C81 C83 C93 C98 C102-C104 C106 C108 C110 = GRM188R61E475KE11D: as C49 on sheet CAMERA 2
C84 C85 = GRM188R72A104KA35D: as C52 on sheet CAMERA 2
C86 = GRM21BR61C106KE15L: as C54 on sheet CAMERA 2
C90 = GRM155R71C473KA01D: as C58 on sheet CAMERA 2
C107 = JMK212BJ226KG-T: as C75 on sheet CAMERA 2
CN9 = 59S10H-40ML5-Y: as CN7 on sheet CAMERA 2
CN10 = D4S10A-400L5-Z: Straight Plug; Manufacturer: Rosenberger
L24 L25 = 1008PS-103KLB: as L14 on sheet CAMERA 2
L26 = DLW21HN670SQ2L: as L16 on sheet CAMERA 2
L27 = BLM18AG102SN1D: as L17 on sheet CAMERA 2
L28 = 1008PS-472KLB: as L18 on sheet CAMERA 2
L29 = MSS7341T-104MLB: as L19 on sheet CAMERA 2
L30-L33 = BLM15AX102SN1D: as L20-L23 on sheet CAMERA 2
R74-R76 = CRCW08050000Z0EA: as R50-R52 on sheet CAMERA 2
R77 R78 = RC0603JR-071KL: as R53 on sheet CAMERA 2
R79-R81 = CRCW040249R9FKED: as R55-R57 on sheet CAMERA 2
R82 R85 R86 = CRCW040233R0JNED: as R58 on sheet CAMERA 2
R83 R84 R92 R93 R175 = ERA-2AEB103X: as R59 on sheet CAMERA 2
R87 R95 = CRCW04020000Z0ED: as R63 on sheet CAMERA 2
R88 R97 = CRCW040211K0FKED: as R73 on sheet CAMERA 2
R89-R91 R94 = CRCW04022K20JNED: as R65-R67 on sheet CAMERA 2
R96 = CRCW04023K01FKED: as R64 on sheet CAMERA 2
R173 R174 = CRCW0402130RJNED: as R170 on sheet CAMERA 2
TP9-TP12 = TP-032_RND: Test Point, O.032 Hole
TR3 = TPD2E001DRLR: as TR2 on sheet CAMERA 2
U11 = DS90UB914ATRHSTQ1: as U10 on sheet CAMERA 2

## Sheet CAMERA 4.SchDoc
size 431 x 279 mm; Date: Not shown in title block; ApprovedBy: Not shown in title block; CheckedBy: Not shown in title block; Author: Not shown in title block; CompanyName: Not shown in title block; DrawnBy: G. Fiolic; Engineer: Not shown in title block; Organization: Not shown in title block; Address1: Not shown in title block; Address2: Not shown in title block; Address3: Not shown in title block; Address4: Not shown in title block; DocumentNumber: 8; Revision: Use project parameter SCH_Rev; SheetNumber: 8; SheetTotal: 11; PageSetup: Record=PageOptions|CenterHorizontal=True|CenterVertical=True|PrintScale=1.00|XCorrection=1.00|YCorrection=1.00|PrintKind=0|BorderSize=5000000|LeftOffset=0|BottomOffset=0|Orientation=2|PaperLength=1000|PaperWidth=1000|Scale=100|PaperSource=15|PrintQuality=600|MediaType=1|DitherType=10|PaperKind=Letter|PrintScaleMode=1
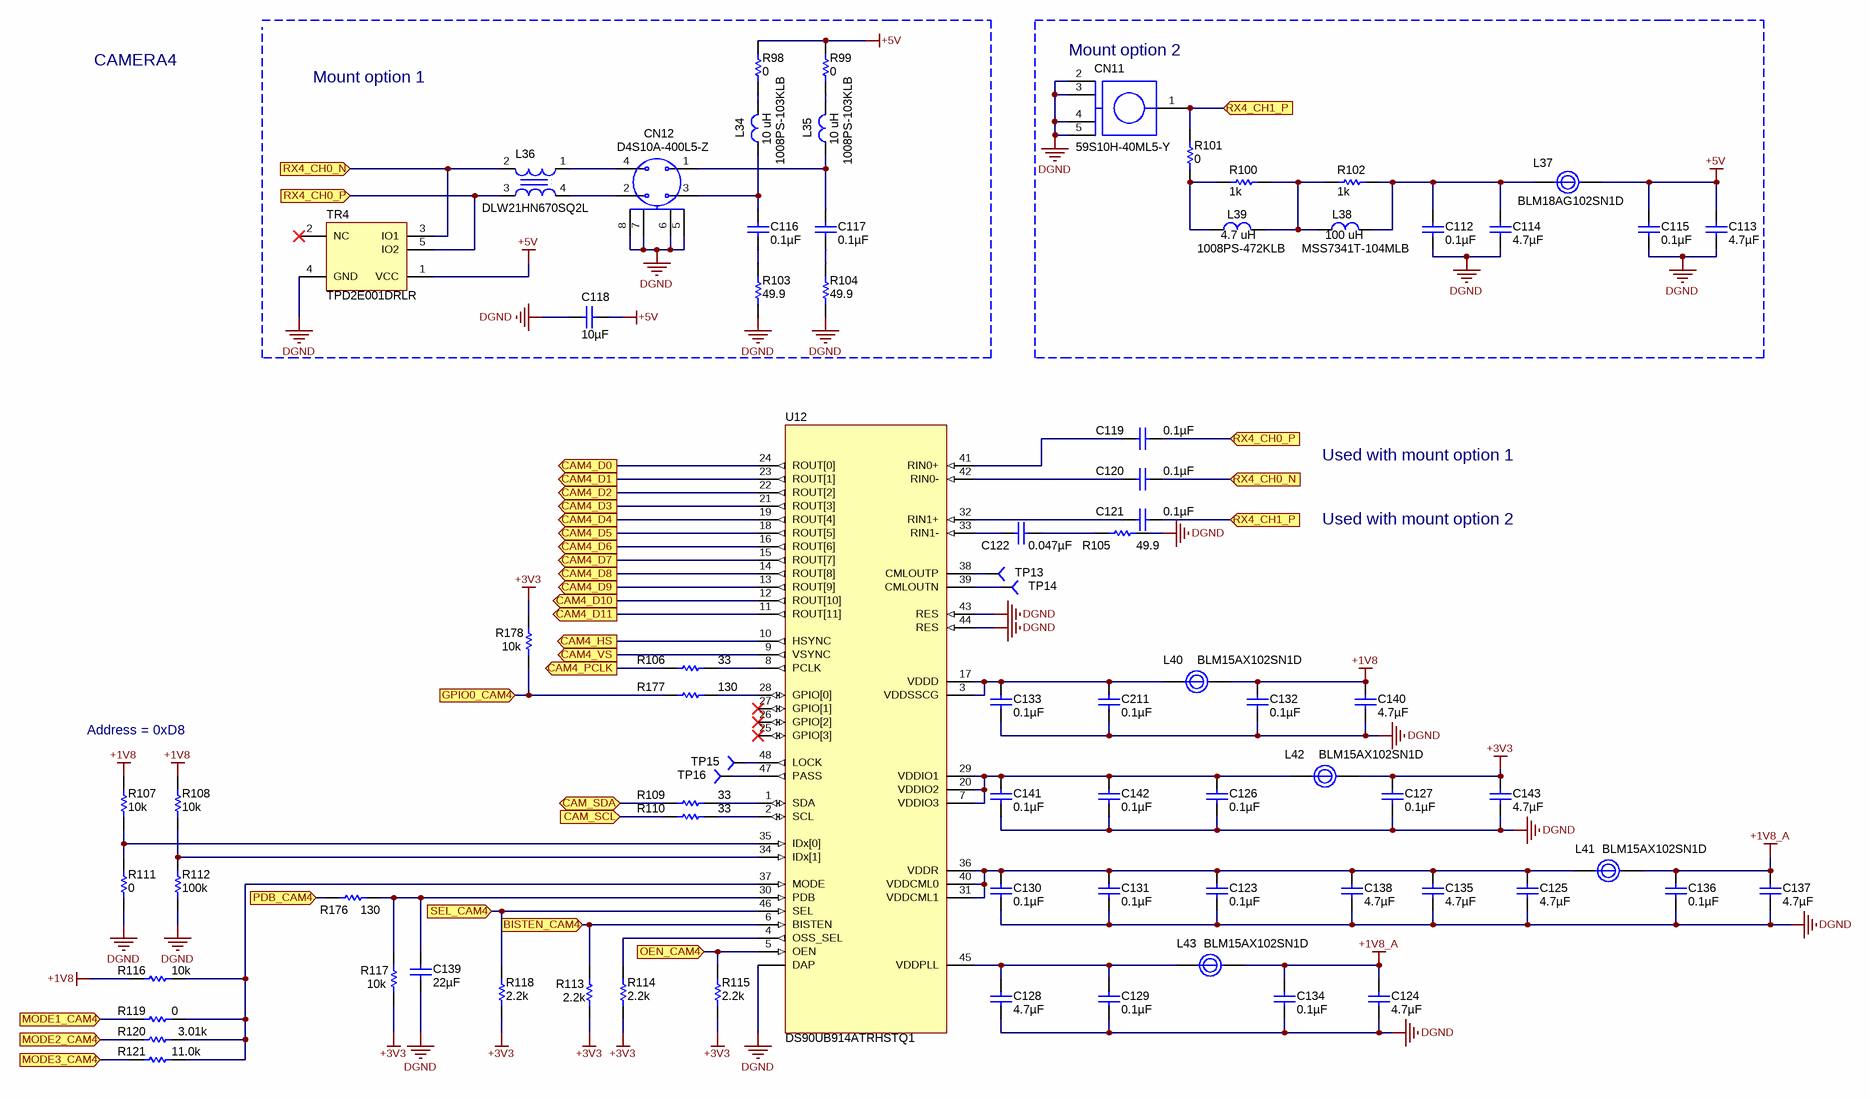
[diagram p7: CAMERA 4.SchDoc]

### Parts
C112  ValueDisplayed: 0.1µF  [0402L]  (hidden comment: GRM155R71C104KA88D)
C113  value 4.7µF  [0603L]  (hidden comment: GRM188R61E475KE11D)
C114  value 4.7µF  [0603L]  (hidden comment: GRM188R61E475KE11D)
C115  ValueDisplayed: 0.1µF  [0402L]  (hidden comment: GRM155R71C104KA88D)
C116  value 0.1µF  [0603L]  (hidden comment: GRM188R72A104KA35D)
C117  value 0.1µF  [0603L]  (hidden comment: GRM188R72A104KA35D)
C118  ValueDisplayed: 10µF  [0805L]  (hidden comment: GRM21BR61C106KE15L)
C119  ValueDisplayed: 0.1µF  [0402L]  (hidden comment: GRM155R71C104KA88D)
C120  ValueDisplayed: 0.1µF  [0402L]  (hidden comment: GRM155R71C104KA88D)
C121  ValueDisplayed: 0.1µF  [0402L]  (hidden comment: GRM155R71C104KA88D)
C122  ValueDisplayed: 0.047µF  [0402L]  (hidden comment: GRM155R71C473KA01D)
C123  ValueDisplayed: 0.1µF  [0402L]  (hidden comment: GRM155R71C104KA88D)
C124  value 4.7µF  [0603L]  (hidden comment: GRM188R61E475KE11D)
C125  value 4.7µF  [0603L]  (hidden comment: GRM188R61E475KE11D)
C126  ValueDisplayed: 0.1µF  [0402L]  (hidden comment: GRM155R71C104KA88D)
C127  ValueDisplayed: 0.1µF  [0402L]  (hidden comment: GRM155R71C104KA88D)
C128  value 4.7µF  [0603L]  (hidden comment: GRM188R61E475KE11D)
C129  ValueDisplayed: 0.1µF  [0402L]  (hidden comment: GRM155R71C104KA88D)
C130  ValueDisplayed: 0.1µF  [0402L]  (hidden comment: GRM155R71C104KA88D)
C131  ValueDisplayed: 0.1µF  [0402L]  (hidden comment: GRM155R71C104KA88D)
C132  ValueDisplayed: 0.1µF  [0402L]  (hidden comment: GRM155R71C104KA88D)
C133  ValueDisplayed: 0.1µF  [0402L]  (hidden comment: GRM155R71C104KA88D)
C134  ValueDisplayed: 0.1µF  [0402L]  (hidden comment: GRM155R71C104KA88D)
C135  value 4.7µF  [0603L]  (hidden comment: GRM188R61E475KE11D)
C136  ValueDisplayed: 0.1µF  [0402L]  (hidden comment: GRM155R71C104KA88D)
C137  value 4.7µF  [0603L]  (hidden comment: GRM188R61E475KE11D)
C138  value 4.7µF  [0603L]  (hidden comment: GRM188R61E475KE11D)
C139  ValueDisplayed: 22µF  [0805L]  (hidden comment: JMK212BJ226KG-T)
C140  value 4.7µF  [0603L]  (hidden comment: GRM188R61E475KE11D)
C141  ValueDisplayed: 0.1µF  [0402L]  (hidden comment: GRM155R71C104KA88D)
C142  ValueDisplayed: 0.1µF  [0402L]  (hidden comment: GRM155R71C104KA88D)
C143  value 4.7µF  [0603L]  (hidden comment: GRM188R61E475KE11D)
C211  ValueDisplayed: 0.1µF  [0402L]  (hidden comment: GRM155R71C104KA88D)
CN11  59S10H-40ML5-Y  [59S10H-40ML5-Y]
CN12  D4S10A-400L5-Z  [D4S10A-400L5-Z]
L34  1008PS-103KLB  ValueDisplayed: 10 uH  [1008PS-103KLB]
L35  1008PS-103KLB  ValueDisplayed: 10 uH  [1008PS-103KLB]
L36  DLW21HN670SQ2L  [DLW21HN670SQ2L]
L37  BLM18AG102SN1D  [0603L]
L38  ValueDisplayed: 100 uH  [MSS7341T-104MLB]  (hidden comment: MSS7341T-104MLB)
L39  ValueDisplayed: 4.7 uH  [1008PS-472KLB]  (hidden comment: 1008PS-472KLB)
L40  BLM15AX102SN1D  [0402L]
L41  BLM15AX102SN1D  [0402L]
L42  BLM15AX102SN1D  [0402L]
L43  BLM15AX102SN1D  [0402L]
R98  value 0  [0805L]  (hidden comment: CRCW08050000Z0EA)
R99  value 0  [0805L]  (hidden comment: CRCW08050000Z0EA)
R100  value 1k  [0603L]  (hidden comment: RC0603JR-071KL)
R101  value 0  [0805L]  (hidden comment: CRCW08050000Z0EA)
R102  value 1k  [0603L]  (hidden comment: RC0603JR-071KL)
R103  value 49.9  [0402L]  (hidden comment: CRCW040249R9FKED)
R104  value 49.9  [0402L]  (hidden comment: CRCW040249R9FKED)
R105  value 49.9  [0402L]  (hidden comment: CRCW040249R9FKED)
R106  value 33  [0402L]  (hidden comment: CRCW040233R0JNED)
R107  value 10k  [0402L]  (hidden comment: ERA-2AEB103X)
R108  value 10k  [0402L]  (hidden comment: ERA-2AEB103X)
R109  value 33  [0402L]  (hidden comment: CRCW040233R0JNED)
R110  value 33  [0402L]  (hidden comment: CRCW040233R0JNED)
R111  value 0  [0402L]  (hidden comment: CRCW04020000Z0ED)
R112  value 100k  [0402L]  (hidden comment: CRCW0402100KFKED)
R113  value 2.2k  [0402L]  (hidden comment: CRCW04022K20JNED)
R114  value 2.2k  [0402L]  (hidden comment: CRCW04022K20JNED)
R115  value 2.2k  [0402L]  (hidden comment: CRCW04022K20JNED)
R116  value 10k  [0402L]  (hidden comment: ERA-2AEB103X)
R117  value 10k  [0402L]  (hidden comment: ERA-2AEB103X)
R118  value 2.2k  [0402L]  (hidden comment: CRCW04022K20JNED)
R119  value 0  [0402L]  (hidden comment: CRCW04020000Z0ED)
R120  value 3.01k  [0402L]  (hidden comment: CRCW04023K01FKED)
R121  value 11.0k  [0402L]  (hidden comment: CRCW040211K0FKED)
R176  value 130  [0402L]  (hidden comment: CRCW0402130RJNED)
R177  value 130  [0402L]  (hidden comment: CRCW0402130RJNED)
R178  value 10k  [0402L]  (hidden comment: ERA-2AEB103X)
TP13  STD  [TP-032_RND]  (value not drawn)
TP14  STD  [TP-032_RND]  (value not drawn)
TP15  STD  [TP-032_RND]  (value not drawn)
TP16  STD  [TP-032_RND]  (value not drawn)
TR4  TPD2E001DRLR  [DRL0005A]
U12  DS90UB914ATRHSTQ1  [RHS0048A]

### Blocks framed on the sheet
Mount option 2: C112-C115 CN11 L37-L39 R100-R102

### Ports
BISTEN_CAM4 (in), CAM4_D0 (out), CAM4_D1 (out), CAM4_D2 (out), CAM4_D3 (out), CAM4_D4 (out), CAM4_D5 (out), CAM4_D6 (out), CAM4_D7 (out), CAM4_D8 (out), CAM4_D9 (out), CAM4_D10 (out), CAM4_D11 (out), CAM4_HS (out), CAM4_PCLK (out), CAM4_VS (out), CAM_SCL (in), CAM_SDA (bidir), GPIO0_CAM4 (in), MODE1_CAM4 (in), MODE2_CAM4 (in), MODE3_CAM4 (in), OEN_CAM4 (in), PDB_CAM4 (in), RX4_CH0_N (in), RX4_CH0_P (in), RX4_CH1_P (in), SEL_CAM4 (in)

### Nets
+1V8: C132.1 C140.1 L40.2 R107.1 R108.1 R116.1
+1V8_A: C124.1 C134.1 C136.1 C137.1 L41.2 L43.2
+3V3: C127.1 C143.1 L42.2 R113.2 R114.2 R115.2 R117.1 R118.1 R178.1
+5V: C113.1 C115.1 C118.1 L37.2 R98.2 R99.2 TR4.1(VCC)
DGND: C112.2 C113.2 C114.2 C115.2 C118.2 C123.2 C124.2 C125.2 C126.2 C127.2 C128.2 C129.2 C130.2 C131.2 C132.2 C133.2 C134.2 C135.2 C136.2 C137.2 C138.2 C139.2 C140.2 C141.2 C142.2 C143.2 C211.2 CN11.2 CN11.3 CN11.4 CN11.5 CN12.5 CN12.6 CN12.7 CN12.8 R103.1 R104.1 R105.2 R111.2 R112.2 TR4.4(GND) U12.43(RES) U12.44(RES) U12.49(DAP)
BISTEN_CAM4: R113.1 R118.2 U12.6(BISTEN) U12.46(SEL) ; port SEL_CAM4, port BISTEN_CAM4
CAM4_D0: U12.24(ROUT[0]) ; port CAM4_D0
CAM4_D1: U12.23(ROUT[1]) ; port CAM4_D1
CAM4_D2: U12.22(ROUT[2]) ; port CAM4_D2
CAM4_D3: U12.21(ROUT[3]) ; port CAM4_D3
CAM4_D4: U12.19(ROUT[4]) ; port CAM4_D4
CAM4_D5: U12.18(ROUT[5]) ; port CAM4_D5
CAM4_D6: U12.16(ROUT[6]) ; port CAM4_D6
CAM4_D7: U12.15(ROUT[7]) ; port CAM4_D7
CAM4_D8: U12.14(ROUT[8]) ; port CAM4_D8
CAM4_D9: U12.13(ROUT[9]) ; port CAM4_D9
CAM4_D10: U12.12(ROUT[10]) ; port CAM4_D10
CAM4_D11: U12.11(ROUT[11]) ; port CAM4_D11
CAM4_HS: U12.10(HSYNC) ; port CAM4_HS
CAM4_PCLK: R106.1 ; port CAM4_PCLK
CAM4_VS: U12.9(VSYNC) ; port CAM4_VS
CAM_SCL: R110.1 ; port CAM_SCL
CAM_SDA: R109.2 ; port CAM_SDA
GPIO0_CAM4: R177.1 R178.2 ; port GPIO0_CAM4
MODE1_CAM4: R119.1 ; port MODE1_CAM4
MODE2_CAM4: R120.1 ; port MODE2_CAM4
MODE3_CAM4: R121.1 ; port MODE3_CAM4
OEN_CAM4: R115.1 U12.5(OEN) ; port OEN_CAM4
PDB_CAM4: R176.1 ; port PDB_CAM4
RX4_CH0_N: C120.2 L36.2(IN2) TR4.3(IO1) ; port RX4_CH0_N
RX4_CH0_P: C119.2 L36.3(OUT2) TR4.5(IO2) ; port RX4_CH0_P
RX4_CH1_P: C121.2 CN11.1 R101.2 ; port RX4_CH1_P
NetC112_1: C112.1 C114.1 L37.1 L38.2 R102.2
NetC116_1: C116.1 CN12.3 L34.2
NetC116_2: C116.2 R103.2
NetC117_1: C117.1 CN12.1 L35.2
NetC117_2: C117.2 R104.2
NetC119_1: C119.1 U12.41(RIN0+)
NetC120_1: C120.1 U12.42(RIN0-)
NetC121_1: C121.1 U12.32(RIN1+)
NetC122_1: C122.1 U12.33(RIN1-)
NetC122_2: C122.2 R105.1
NetC123_1: C123.1 C125.1 C130.1 C131.1 C135.1 C138.1 L41.1 U12.31(VDDCML1) U12.36(VDDR) U12.40(VDDCML0)
NetC126_1: C126.1 C141.1 C142.1 L42.1 U12.7(VDDIO3) U12.20(VDDIO2) U12.29(VDDIO1)
NetC128_1: C128.1 C129.1 L43.1 U12.45(VDDPLL)
NetC133_1: C133.1 C211.1 L40.1 U12.3(VDDSSCG) U12.17(VDDD)
NetC139_1: C139.1 R117.2 R176.2 U12.30(PDB)
NetCN12_2: CN12.2 L36.4(OUT1)
NetCN12_4: CN12.4 L36.1(IN1)
NetL34_1: L34.1 R98.1
NetL35_1: L35.1 R99.1
NetL38_1: L38.1 L39.2 R100.2 R102.1
NetL39_1: L39.1 R100.1 R101.1
NetR106_2: R106.2 U12.8(PCLK)
NetR107_2: R107.2 R111.1 U12.35(IDx[0])
NetR108_2: R108.2 R112.1 U12.34(IDx[1])
NetR109_1: R109.1 U12.1(SDA)
NetR110_2: R110.2 U12.2(SCL)
NetR114_1: R114.1 U12.4(OSS_SEL)
NetR116_2: R116.2 R119.2 R120.2 R121.2 U12.37(MODE)
NetR177_2: R177.2 U12.28(GPIO[0])
NetTP13_1: TP13.1 U12.38(CMLOUTP)
NetTP14_1: TP14.1 U12.39(CMLOUTN)
NetTP15_1: TP15.1 U12.48(LOCK)
NetTP16_1: TP16.1 U12.47(PASS)

Not connected (* = marked no-connect by the designer): TR4 2(NC)*; U12 25(GPIO[3])* 26(GPIO[2])* 27(GPIO[1])*

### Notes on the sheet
- CAMERA4
- Mount option 1
- Used with mount option 1
- Used with mount option 2
- Address = 0xD8

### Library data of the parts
C112 C115 C119-C121 C123 C126 C127 C129-C134 C136 C141 C142 C211 = GRM155R71C104KA88D: as C48 on sheet CAMERA 2
C113 C114 C124 C125 C128 C135 C137 C138 C140 C143 = GRM188R61E475KE11D: as C49 on sheet CAMERA 2
C116 C117 = GRM188R72A104KA35D: as C52 on sheet CAMERA 2
C118 = GRM21BR61C106KE15L: as C54 on sheet CAMERA 2
C122 = GRM155R71C473KA01D: as C58 on sheet CAMERA 2
C139 = JMK212BJ226KG-T: as C75 on sheet CAMERA 2
CN11 = 59S10H-40ML5-Y: as CN7 on sheet CAMERA 2
CN12 = D4S10A-400L5-Z: Straight Plug; Manufacturer: Rosenberger
L34 L35 = 1008PS-103KLB: as L14 on sheet CAMERA 2
L36 = DLW21HN670SQ2L: as L16 on sheet CAMERA 2
L37 = BLM18AG102SN1D: as L17 on sheet CAMERA 2
L38 = MSS7341T-104MLB: as L19 on sheet CAMERA 2
L39 = 1008PS-472KLB: as L18 on sheet CAMERA 2
L40-L43 = BLM15AX102SN1D: as L20-L23 on sheet CAMERA 2
R98 R99 R101 = CRCW08050000Z0EA: as R50-R52 on sheet CAMERA 2
R100 R102 = RC0603JR-071KL: as R53 on sheet CAMERA 2
R103-R105 = CRCW040249R9FKED: as R55-R57 on sheet CAMERA 2
R106 R109 R110 = CRCW040233R0JNED: as R58 on sheet CAMERA 2
R107 R108 R116 R117 R178 = ERA-2AEB103X: as R59 on sheet CAMERA 2
R111 R119 = CRCW04020000Z0ED: as R63 on sheet CAMERA 2
R112 = CRCW0402100KFKED: RES, 100k ohm, 1%, 0.063W, 0402; Manufacturer: Vishay-Dale; CompType: Resistor; Res_ohm: 100000; Tolerance_%: 1; Power_W: 0.063; VDC_V: 50; TempCo: 100 ppm/C; EIA_Code: E96; U/M: EA
R113-R115 R118 = CRCW04022K20JNED: as R65-R67 on sheet CAMERA 2
R120 = CRCW04023K01FKED: as R64 on sheet CAMERA 2
R121 = CRCW040211K0FKED: as R73 on sheet CAMERA 2
R176 R177 = CRCW0402130RJNED: as R170 on sheet CAMERA 2
TP13-TP16 = TP-032_RND: Test Point, O.032 Hole
TR4 = TPD2E001DRLR: as TR2 on sheet CAMERA 2
U12 = DS90UB914ATRHSTQ1: as U10 on sheet CAMERA 2

## Sheet CAMERA 5.SchDoc
size 431 x 279 mm; Date: Not shown in title block; ApprovedBy: Not shown in title block; CheckedBy: Not shown in title block; Author: Not shown in title block; CompanyName: Not shown in title block; DrawnBy: G. Fiolic; Engineer: Not shown in title block; Organization: Not shown in title block; Address1: Not shown in title block; Address2: Not shown in title block; Address3: Not shown in title block; Address4: Not shown in title block; DocumentNumber: 9; Revision: Use project parameter SCH_Rev; SheetNumber: 9; SheetTotal: 11; PageSetup: Record=PageOptions|CenterHorizontal=True|CenterVertical=True|PrintScale=1.00|XCorrection=1.00|YCorrection=1.00|PrintKind=0|BorderSize=5000000|LeftOffset=0|BottomOffset=0|Orientation=2|PaperLength=1000|PaperWidth=1000|Scale=100|PaperSource=15|PrintQuality=600|MediaType=1|DitherType=10|PaperKind=Letter|PrintScaleMode=1
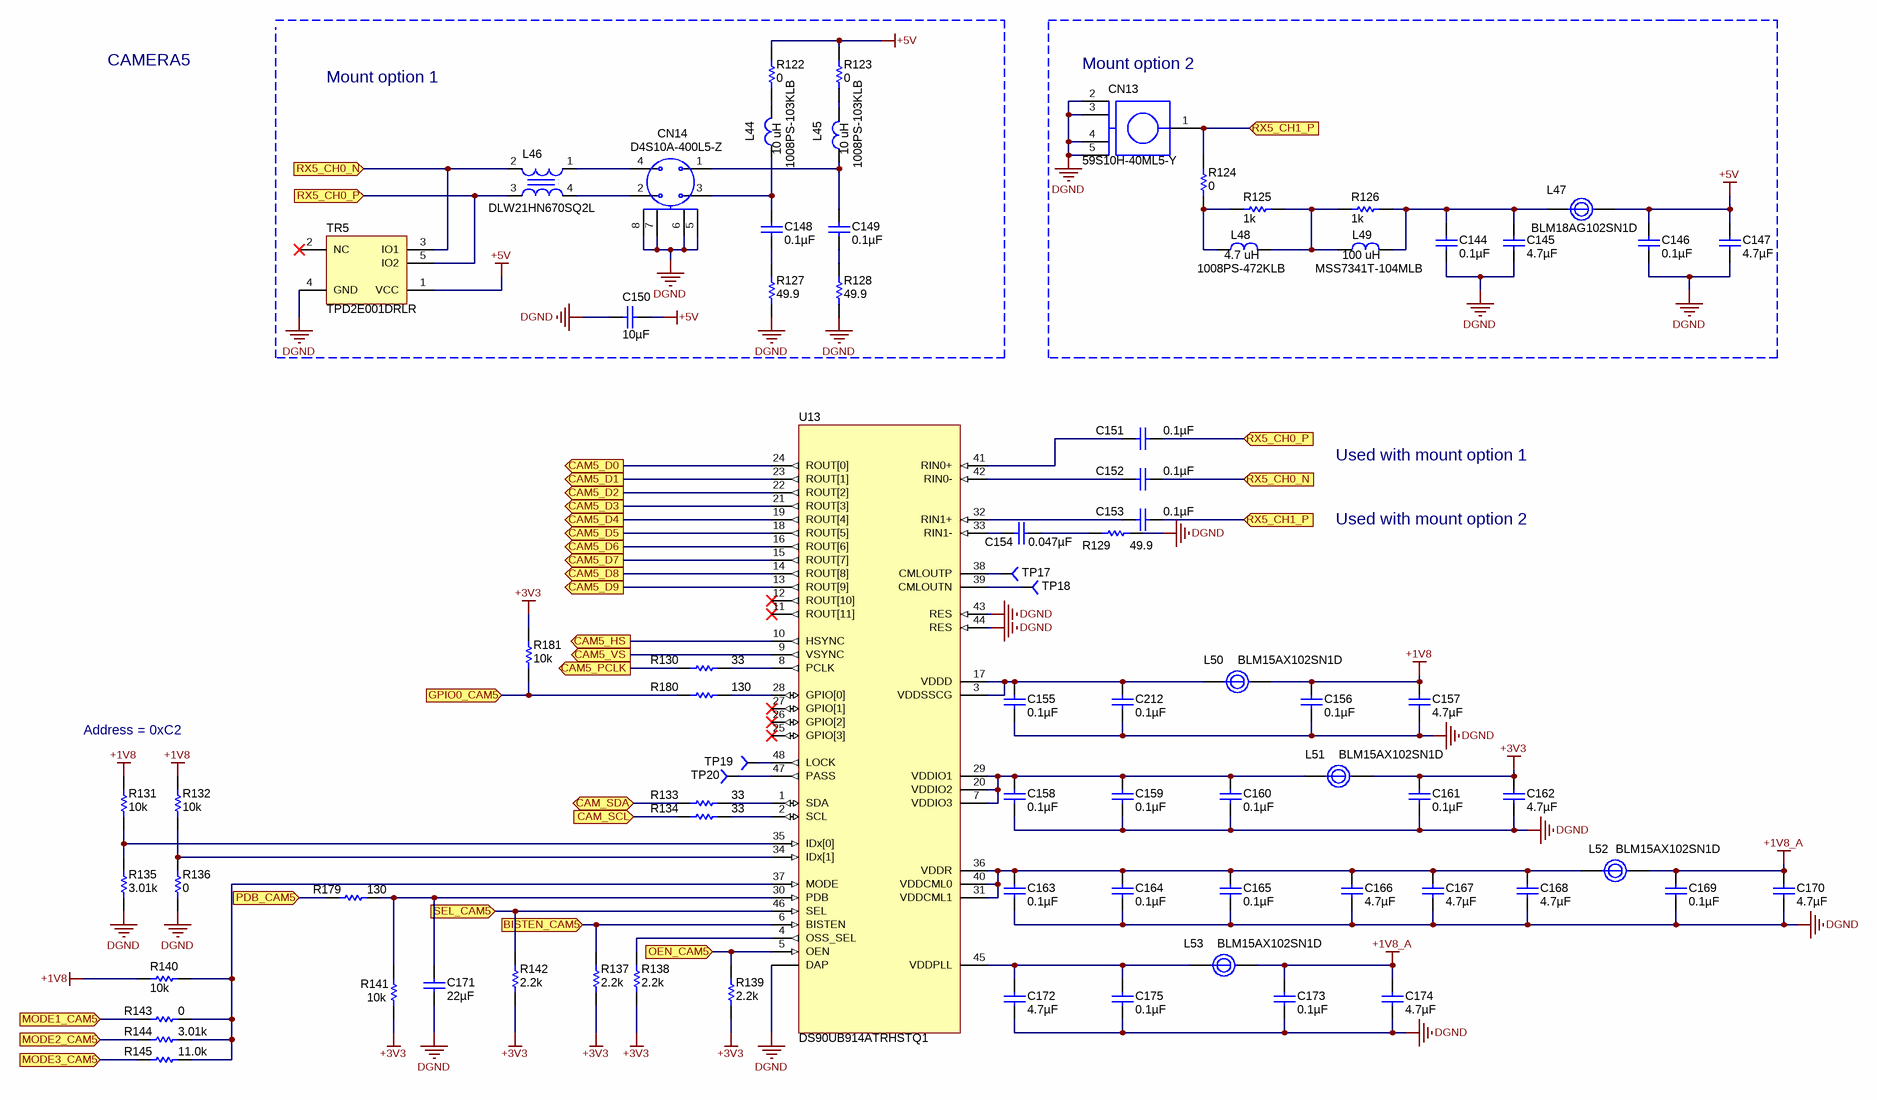
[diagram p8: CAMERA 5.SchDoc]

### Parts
C144  ValueDisplayed: 0.1µF  [0402L]  (hidden comment: GRM155R71C104KA88D)
C145  value 4.7µF  [0603L]  (hidden comment: GRM188R61E475KE11D)
C146  ValueDisplayed: 0.1µF  [0402L]  (hidden comment: GRM155R71C104KA88D)
C147  value 4.7µF  [0603L]  (hidden comment: GRM188R61E475KE11D)
C148  value 0.1µF  [0603L]  (hidden comment: GRM188R72A104KA35D)
C149  value 0.1µF  [0603L]  (hidden comment: GRM188R72A104KA35D)
C150  ValueDisplayed: 10µF  [0805L]  (hidden comment: GRM21BR61C106KE15L)
C151  ValueDisplayed: 0.1µF  [0402L]  (hidden comment: GRM155R71C104KA88D)
C152  ValueDisplayed: 0.1µF  [0402L]  (hidden comment: GRM155R71C104KA88D)
C153  ValueDisplayed: 0.1µF  [0402L]  (hidden comment: GRM155R71C104KA88D)
C154  ValueDisplayed: 0.047µF  [0402L]  (hidden comment: GRM155R71C473KA01D)
C155  ValueDisplayed: 0.1µF  [0402L]  (hidden comment: GRM155R71C104KA88D)
C156  ValueDisplayed: 0.1µF  [0402L]  (hidden comment: GRM155R71C104KA88D)
C157  value 4.7µF  [0603L]  (hidden comment: GRM188R61E475KE11D)
C158  ValueDisplayed: 0.1µF  [0402L]  (hidden comment: GRM155R71C104KA88D)
C159  ValueDisplayed: 0.1µF  [0402L]  (hidden comment: GRM155R71C104KA88D)
C160  ValueDisplayed: 0.1µF  [0402L]  (hidden comment: GRM155R71C104KA88D)
C161  ValueDisplayed: 0.1µF  [0402L]  (hidden comment: GRM155R71C104KA88D)
C162  value 4.7µF  [0603L]  (hidden comment: GRM188R61E475KE11D)
C163  ValueDisplayed: 0.1µF  [0402L]  (hidden comment: GRM155R71C104KA88D)
C164  ValueDisplayed: 0.1µF  [0402L]  (hidden comment: GRM155R71C104KA88D)
C165  ValueDisplayed: 0.1µF  [0402L]  (hidden comment: GRM155R71C104KA88D)
C166  value 4.7µF  [0603L]  (hidden comment: GRM188R61E475KE11D)
C167  value 4.7µF  [0603L]  (hidden comment: GRM188R61E475KE11D)
C168  value 4.7µF  [0603L]  (hidden comment: GRM188R61E475KE11D)
C169  ValueDisplayed: 0.1µF  [0402L]  (hidden comment: GRM155R71C104KA88D)
C170  value 4.7µF  [0603L]  (hidden comment: GRM188R61E475KE11D)
C171  ValueDisplayed: 22µF  [0805L]  (hidden comment: JMK212BJ226KG-T)
C172  value 4.7µF  [0603L]  (hidden comment: GRM188R61E475KE11D)
C173  ValueDisplayed: 0.1µF  [0402L]  (hidden comment: GRM155R71C104KA88D)
C174  value 4.7µF  [0603L]  (hidden comment: GRM188R61E475KE11D)
C175  ValueDisplayed: 0.1µF  [0402L]  (hidden comment: GRM155R71C104KA88D)
C212  ValueDisplayed: 0.1µF  [0402L]  (hidden comment: GRM155R71C104KA88D)
CN13  59S10H-40ML5-Y  [59S10H-40ML5-Y]
CN14  D4S10A-400L5-Z  [D4S10A-400L5-Z]
L44  1008PS-103KLB  ValueDisplayed: 10 uH  [1008PS-103KLB]
L45  1008PS-103KLB  ValueDisplayed: 10 uH  [1008PS-103KLB]
L46  DLW21HN670SQ2L  [DLW21HN670SQ2L]
L47  BLM18AG102SN1D  [0603L]
L48  ValueDisplayed: 4.7 uH  [1008PS-472KLB]  (hidden comment: 1008PS-472KLB)
L49  ValueDisplayed: 100 uH  [MSS7341T-104MLB]  (hidden comment: MSS7341T-104MLB)
L50  BLM15AX102SN1D  [0402L]
L51  BLM15AX102SN1D  [0402L]
L52  BLM15AX102SN1D  [0402L]
L53  BLM15AX102SN1D  [0402L]
R122  value 0  [0805L]  (hidden comment: CRCW08050000Z0EA)
R123  value 0  [0805L]  (hidden comment: CRCW08050000Z0EA)
R124  value 0  [0805L]  (hidden comment: CRCW08050000Z0EA)
R125  value 1k  [0603L]  (hidden comment: RC0603JR-071KL)
R126  value 1k  [0603L]  (hidden comment: RC0603JR-071KL)
R127  value 49.9  [0402L]  (hidden comment: CRCW040249R9FKED)
R128  value 49.9  [0402L]  (hidden comment: CRCW040249R9FKED)
R129  value 49.9  [0402L]  (hidden comment: CRCW040249R9FKED)
R130  value 33  [0402L]  (hidden comment: CRCW040233R0JNED)
R131  value 10k  [0402L]  (hidden comment: ERA-2AEB103X)
R132  value 10k  [0402L]  (hidden comment: ERA-2AEB103X)
R133  value 33  [0402L]  (hidden comment: CRCW040233R0JNED)
R134  value 33  [0402L]  (hidden comment: CRCW040233R0JNED)
R135  value 3.01k  [0402L]  (hidden comment: CRCW04023K01FKED)
R136  value 0  [0402L]  (hidden comment: CRCW04020000Z0ED)
R137  value 2.2k  [0402L]  (hidden comment: CRCW04022K20JNED)
R138  value 2.2k  [0402L]  (hidden comment: CRCW04022K20JNED)
R139  value 2.2k  [0402L]  (hidden comment: CRCW04022K20JNED)
R140  value 10k  [0402L]  (hidden comment: ERA-2AEB103X)
R141  value 10k  [0402L]  (hidden comment: ERA-2AEB103X)
R142  value 2.2k  [0402L]  (hidden comment: CRCW04022K20JNED)
R143  value 0  [0402L]  (hidden comment: CRCW04020000Z0ED)
R144  value 3.01k  [0402L]  (hidden comment: CRCW04023K01FKED)
R145  value 11.0k  [0402L]  (hidden comment: CRCW040211K0FKED)
R179  value 130  [0402L]  (hidden comment: CRCW0402130RJNED)
R180  value 130  [0402L]  (hidden comment: CRCW0402130RJNED)
R181  value 10k  [0402L]  (hidden comment: ERA-2AEB103X)
TP17  STD  [TP-032_RND]  (value not drawn)
TP18  STD  [TP-032_RND]  (value not drawn)
TP19  STD  [TP-032_RND]  (value not drawn)
TP20  STD  [TP-032_RND]  (value not drawn)
TR5  TPD2E001DRLR  [DRL0005A]
U13  DS90UB914ATRHSTQ1  [RHS0048A]

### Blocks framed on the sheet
Mount option 2: C144-C147 CN13 L47-L49 R124-R126

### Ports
BISTEN_CAM5 (in), CAM5_D0 (out), CAM5_D1 (out), CAM5_D2 (out), CAM5_D3 (out), CAM5_D4 (out), CAM5_D5 (out), CAM5_D6 (out), CAM5_D7 (out), CAM5_D8 (out), CAM5_D9 (out), CAM5_HS (out), CAM5_PCLK (out), CAM5_VS (out), CAM_SCL (in), CAM_SDA (bidir), GPIO0_CAM5 (in), MODE1_CAM5 (in), MODE2_CAM5 (in), MODE3_CAM5 (in), OEN_CAM5 (in), PDB_CAM5 (in), RX5_CH0_N (in), RX5_CH0_P (in), RX5_CH1_P (in), SEL_CAM5 (in)

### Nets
+1V8: C156.1 C157.1 L50.2 R131.1 R132.1 R140.1
+1V8_A: C169.1 C170.1 C173.1 C174.1 L52.2 L53.2
+3V3: C161.1 C162.1 L51.2 R137.2 R138.2 R139.2 R141.1 R142.1 R181.1
+5V: C146.1 C147.1 C150.1 L47.2 R122.2 R123.2 TR5.1(VCC)
DGND: C144.2 C145.2 C146.2 C147.2 C150.2 C155.2 C156.2 C157.2 C158.2 C159.2 C160.2 C161.2 C162.2 C163.2 C164.2 C165.2 C166.2 C167.2 C168.2 C169.2 C170.2 C171.2 C172.2 C173.2 C174.2 C175.2 C212.2 CN13.2 CN13.3 CN13.4 CN13.5 CN14.5 CN14.6 CN14.7 CN14.8 R127.1 R128.1 R129.2 R135.2 R136.2 TR5.4(GND) U13.43(RES) U13.44(RES) U13.49(DAP)
BISTEN_CAM5: R137.1 U13.6(BISTEN) ; port BISTEN_CAM5
CAM5_D0: U13.24(ROUT[0]) ; port CAM5_D0
CAM5_D1: U13.23(ROUT[1]) ; port CAM5_D1
CAM5_D2: U13.22(ROUT[2]) ; port CAM5_D2
CAM5_D3: U13.21(ROUT[3]) ; port CAM5_D3
CAM5_D4: U13.19(ROUT[4]) ; port CAM5_D4
CAM5_D5: U13.18(ROUT[5]) ; port CAM5_D5
CAM5_D6: U13.16(ROUT[6]) ; port CAM5_D6
CAM5_D7: U13.15(ROUT[7]) ; port CAM5_D7
CAM5_D8: U13.14(ROUT[8]) ; port CAM5_D8
CAM5_D9: U13.13(ROUT[9]) ; port CAM5_D9
CAM5_HS: U13.10(HSYNC) ; port CAM5_HS
CAM5_PCLK: R130.1 ; port CAM5_PCLK
CAM5_VS: U13.9(VSYNC) ; port CAM5_VS
CAM_SCL: R134.1 ; port CAM_SCL
CAM_SDA: R133.2 ; port CAM_SDA
GPIO0_CAM5: R180.1 R181.2 ; port GPIO0_CAM5
MODE1_CAM5: R143.1 ; port MODE1_CAM5
MODE2_CAM5: R144.1 ; port MODE2_CAM5
MODE3_CAM5: R145.1 ; port MODE3_CAM5
OEN_CAM5: R139.1 U13.5(OEN) ; port OEN_CAM5
PDB_CAM5: R179.1 ; port PDB_CAM5
RX5_CH0_N: C152.2 L46.2(IN2) TR5.3(IO1) ; port RX5_CH0_N
RX5_CH0_P: C151.2 L46.3(OUT2) TR5.5(IO2) ; port RX5_CH0_P
RX5_CH1_P: C153.2 CN13.1 R124.2 ; port RX5_CH1_P
SEL_CAM5: R142.2 U13.46(SEL) ; port SEL_CAM5
NetC144_1: C144.1 C145.1 L47.1 L49.2 R126.2
NetC148_1: C148.1 CN14.3 L44.2
NetC148_2: C148.2 R127.2
NetC149_1: C149.1 CN14.1 L45.2
NetC149_2: C149.2 R128.2
NetC151_1: C151.1 U13.41(RIN0+)
NetC152_1: C152.1 U13.42(RIN0-)
NetC153_1: C153.1 U13.32(RIN1+)
NetC154_1: C154.1 R129.1
NetC154_2: C154.2 U13.33(RIN1-)
NetC155_1: C155.1 C212.1 L50.1 U13.3(VDDSSCG) U13.17(VDDD)
NetC158_1: C158.1 C159.1 C160.1 L51.1 U13.7(VDDIO3) U13.20(VDDIO2) U13.29(VDDIO1)
NetC163_1: C163.1 C164.1 C165.1 C166.1 C167.1 C168.1 L52.1 U13.31(VDDCML1) U13.36(VDDR) U13.40(VDDCML0)
NetC171_1: C171.1 R141.2 R179.2 U13.30(PDB)
NetC172_1: C172.1 C175.1 L53.1 U13.45(VDDPLL)
NetCN14_2: CN14.2 L46.4(OUT1)
NetCN14_4: CN14.4 L46.1(IN1)
NetL44_1: L44.1 R122.1
NetL45_1: L45.1 R123.1
NetL48_1: L48.1 R124.1 R125.1
NetL48_2: L48.2 L49.1 R125.2 R126.1
NetR130_2: R130.2 U13.8(PCLK)
NetR131_2: R131.2 R135.1 U13.35(IDx[0])
NetR132_2: R132.2 R136.1 U13.34(IDx[1])
NetR133_1: R133.1 U13.1(SDA)
NetR134_2: R134.2 U13.2(SCL)
NetR138_1: R138.1 U13.4(OSS_SEL)
NetR140_2: R140.2 R143.2 R144.2 R145.2 U13.37(MODE)
NetR180_2: R180.2 U13.28(GPIO[0])
NetTP17_1: TP17.1 U13.38(CMLOUTP)
NetTP18_1: TP18.1 U13.39(CMLOUTN)
NetTP19_1: TP19.1 U13.48(LOCK)
NetTP20_1: TP20.1 U13.47(PASS)

Not connected (* = marked no-connect by the designer): TR5 2(NC)*; U13 11(ROUT[11])* 12(ROUT[10])* 25(GPIO[3])* 26(GPIO[2])* 27(GPIO[1])*

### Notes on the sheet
- CAMERA5
- Mount option 1
- Used with mount option 1
- Used with mount option 2
- Address = 0xC2

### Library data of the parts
C144 C146 C151-C153 C155 C156 C158-C161 C163-C165 C169 C173 C175 C212 = GRM155R71C104KA88D: as C48 on sheet CAMERA 2
C145 C147 C157 C162 C166-C168 C170 C172 C174 = GRM188R61E475KE11D: as C49 on sheet CAMERA 2
C148 C149 = GRM188R72A104KA35D: as C52 on sheet CAMERA 2
C150 = GRM21BR61C106KE15L: as C54 on sheet CAMERA 2
C154 = GRM155R71C473KA01D: as C58 on sheet CAMERA 2
C171 = JMK212BJ226KG-T: as C75 on sheet CAMERA 2
CN13 = 59S10H-40ML5-Y: as CN7 on sheet CAMERA 2
CN14 = D4S10A-400L5-Z: Straight Plug; Manufacturer: Rosenberger
L44 L45 = 1008PS-103KLB: as L14 on sheet CAMERA 2
L46 = DLW21HN670SQ2L: as L16 on sheet CAMERA 2
L47 = BLM18AG102SN1D: as L17 on sheet CAMERA 2
L48 = 1008PS-472KLB: as L18 on sheet CAMERA 2
L49 = MSS7341T-104MLB: as L19 on sheet CAMERA 2
L50-L53 = BLM15AX102SN1D: as L20-L23 on sheet CAMERA 2
R122-R124 = CRCW08050000Z0EA: as R50-R52 on sheet CAMERA 2
R125 R126 = RC0603JR-071KL: as R53 on sheet CAMERA 2
R127-R129 = CRCW040249R9FKED: as R55-R57 on sheet CAMERA 2
R130 R133 R134 = CRCW040233R0JNED: as R58 on sheet CAMERA 2
R131 R132 R140 R141 R181 = ERA-2AEB103X: as R59 on sheet CAMERA 2
R135 R144 = CRCW04023K01FKED: as R64 on sheet CAMERA 2
R136 R143 = CRCW04020000Z0ED: as R63 on sheet CAMERA 2
R137-R139 R142 = CRCW04022K20JNED: as R65-R67 on sheet CAMERA 2
R145 = CRCW040211K0FKED: as R73 on sheet CAMERA 2
R179 R180 = CRCW0402130RJNED: as R170 on sheet CAMERA 2
TP17-TP20 = TP-032_RND: Test Point, O.032 Hole
TR5 = TPD2E001DRLR: as TR2 on sheet CAMERA 2
U13 = DS90UB914ATRHSTQ1: as U10 on sheet CAMERA 2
